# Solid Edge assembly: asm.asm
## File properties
Author: Deepak Maini
Template: Normal.asm
Last saved by: CADCIM
Revision: 5
Application: Solid Edge
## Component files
endplatemod.par
diskmod.par
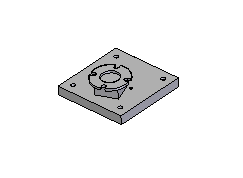
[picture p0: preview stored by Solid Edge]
